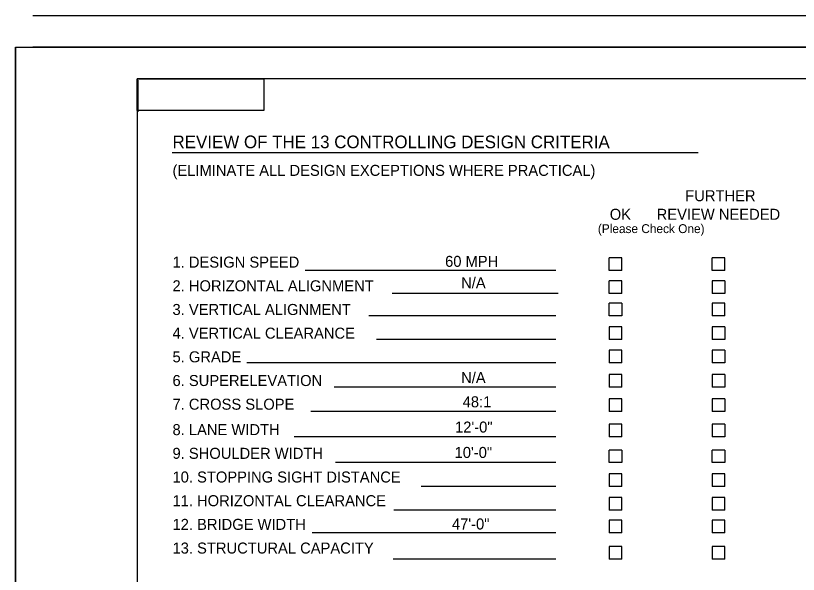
# Model space of a CAD drawing. Extents: x -12279 to -10482, y 3228 to 4378.
# Drawn here: x -12278 to -11660, y 3937 to 4378 of the extents above; entities that cross this region are included whole.
import ezdxf

# ---------------------------------------------------------------- set-up
doc = ezdxf.new("R2010")
doc.units = 0
for name, color, linetype in [('RD_SHT_Bndy', 7, 'Continuous'), ('RD_SHT_IplotShp', 7, 'Continuous'), ('RD_SHT_Snap', 7, 'Continuous'), ('RD_SHT_TX', 7, 'Continuous')]:
    doc.layers.add(name, color=color, linetype=linetype)

msp = doc.modelspace()

# ---------------------------------------------------------------- linework, layer by layer
at = {"layer": 'RD_SHT_Bndy'}
for p, q in [((-10504.69, 4377.98), (-12264.69, 4377.98)), ((-10504.69, 4352.98), (-12264.69, 4352.98)), ((-10507.24, 4327.98), (-12182.24, 4327.98)), ((-12182.24, 4327.98), (-12182.24, 3277.18)), ((-12181.7, 4327.08), (-12181.7, 4302.08)), ((-11738.8, 4269.77), (-12154.49, 4269.77)), ((-11799.22, 4186.64), (-11809.22, 4186.64)), ((-11809.22, 4176.64), (-11809.22, 4186.64)), ((-11799.22, 4176.64), (-11799.22, 4186.64)), ((-11717.68, 4186.64), (-11727.68, 4186.64)), ((-11727.68, 4176.64), (-11727.68, 4186.64)), ((-11717.68, 4176.64), (-11717.68, 4186.64)), ((-11851.36, 4176.64), (-12049.5, 4176.64)), ((-11799.22, 4176.64), (-11809.22, 4176.64)), ((-11717.68, 4176.64), (-11727.68, 4176.64)), ((-11799.22, 4168.7), (-11809.22, 4168.7)), ((-11809.22, 4158.7), (-11809.22, 4168.7)), ((-11799.22, 4158.7), (-11799.22, 4168.7)), ((-11717.68, 4168.7), (-11727.68, 4168.7)), ((-11727.68, 4168.7), (-11727.68, 4158.7)), ((-11717.68, 4168.7), (-11717.68, 4158.7)), ((-11849.4, 4158.7), (-11980.78, 4158.7)), ((-11799.22, 4158.7), (-11809.22, 4158.7)), ((-11717.68, 4158.7), (-11727.68, 4158.7)), ((-11799.22, 4150.89), (-11809.22, 4150.89)), ((-11809.22, 4140.89), (-11809.22, 4150.89)), ((-11799.22, 4150.89), (-11799.22, 4140.89)), ((-11717.68, 4150.89), (-11727.68, 4150.89)), ((-11727.68, 4150.89), (-11727.68, 4140.89)), ((-11717.68, 4140.89), (-11717.68, 4150.89)), ((-11851.36, 4140.89), (-11999.08, 4140.89)), ((-11799.22, 4140.89), (-11809.22, 4140.89)), ((-11717.68, 4140.89), (-11727.68, 4140.89)), ((-11799.22, 4132.2), (-11809.22, 4132.2)), ((-11809.22, 4132.2), (-11809.22, 4122.2)), ((-11799.22, 4122.2), (-11799.22, 4132.2)), ((-11717.68, 4132.2), (-11727.68, 4132.2)), ((-11727.68, 4132.2), (-11727.68, 4122.2)), ((-11717.68, 4132.2), (-11717.68, 4122.2)), ((-11851.36, 4122.2), (-11993.2, 4122.2)), ((-11799.22, 4122.2), (-11809.22, 4122.2)), ((-11717.68, 4122.2), (-11727.68, 4122.2)), ((-11799.22, 4113.86), (-11809.22, 4113.86)), ((-11809.22, 4113.86), (-11809.22, 4103.86)), ((-11799.22, 4103.86), (-11799.22, 4113.86)), ((-11717.68, 4113.86), (-11727.68, 4113.86)), ((-11727.68, 4113.86), (-11727.68, 4103.86)), ((-11717.68, 4113.86), (-11717.68, 4103.86)), ((-11851.36, 4103.86), (-12095.61, 4103.86)), ((-11799.22, 4103.86), (-11809.22, 4103.86)), ((-11717.68, 4103.86), (-11727.68, 4103.86)), ((-11799.22, 4094.62), (-11809.22, 4094.62)), ((-11809.22, 4094.62), (-11809.22, 4084.62)), ((-11799.22, 4084.62), (-11799.22, 4094.62)), ((-11717.68, 4094.62), (-11727.68, 4094.62)), ((-11727.68, 4094.62), (-11727.68, 4084.62)), ((-11717.68, 4094.62), (-11717.68, 4084.62)), ((-11851.36, 4084.62), (-12026.48, 4084.62)), ((-11799.22, 4084.62), (-11809.22, 4084.62)), ((-11717.68, 4084.62), (-11727.68, 4084.62)), ((-11799.22, 4075.28), (-11809.22, 4075.28)), ((-11809.22, 4075.28), (-11809.22, 4065.28)), ((-11799.22, 4065.28), (-11799.22, 4075.28)), ((-11717.68, 4075.28), (-11727.68, 4075.28)), ((-11727.68, 4075.28), (-11727.68, 4065.28)), ((-11717.68, 4075.28), (-11717.68, 4065.28)), ((-11851.36, 4065.28), (-12045.03, 4065.28)), ((-11799.22, 4065.28), (-11809.22, 4065.28)), ((-11717.68, 4065.28), (-11727.68, 4065.28)), ((-11799.22, 4055.4), (-11809.22, 4055.4)), ((-11809.22, 4055.4), (-11809.22, 4045.4)), ((-11799.22, 4045.4), (-11799.22, 4055.4)), ((-11717.68, 4055.4), (-11727.68, 4055.4)), ((-11727.68, 4055.4), (-11727.68, 4045.4)), ((-11717.68, 4055.4), (-11717.68, 4045.4)), ((-11851.36, 4045.4), (-12058.07, 4045.4)), ((-11799.22, 4045.4), (-11809.22, 4045.4)), ((-11717.68, 4045.4), (-11727.68, 4045.4)), ((-11799.22, 4034.99), (-11809.22, 4034.99)), ((-11809.22, 4024.99), (-11809.22, 4034.99)), ((-11799.22, 4034.99), (-11799.22, 4024.99)), ((-11717.68, 4034.99), (-11727.68, 4034.99)), ((-11727.68, 4024.99), (-11727.68, 4034.99)), ((-11717.68, 4034.99), (-11717.68, 4024.99)), ((-11851.36, 4024.99), (-12025.48, 4024.99)), ((-11799.22, 4024.99), (-11809.22, 4024.99)), ((-11717.68, 4024.99), (-11727.68, 4024.99)), ((-11799.22, 4016.19), (-11809.22, 4016.19)), ((-11809.22, 4016.19), (-11809.22, 4006.19)), ((-11799.22, 4006.19), (-11799.22, 4016.19)), ((-11717.68, 4016.19), (-11727.68, 4016.19)), ((-11727.68, 4016.19), (-11727.68, 4006.19)), ((-11717.68, 4006.19), (-11717.68, 4016.19)), ((-11851.36, 4006.19), (-11957.66, 4006.19)), ((-11799.22, 4006.19), (-11809.22, 4006.19)), ((-11717.68, 4006.19), (-11727.68, 4006.19)), ((-11799.22, 3997.39), (-11809.22, 3997.39)), ((-11809.22, 3997.39), (-11809.22, 3987.39)), ((-11799.22, 3987.39), (-11799.22, 3997.39)), ((-11717.68, 3997.39), (-11727.68, 3997.39)), ((-11727.68, 3997.39), (-11727.68, 3987.39)), ((-11717.68, 3987.39), (-11717.68, 3997.39)), ((-11851.36, 3987.39), (-11979.43, 3987.39)), ((-11799.22, 3987.39), (-11809.22, 3987.39)), ((-11717.68, 3987.39), (-11727.68, 3987.39)), ((-11799.22, 3979.66), (-11809.22, 3979.66)), ((-11809.22, 3979.66), (-11809.22, 3969.66)), ((-11799.22, 3969.66), (-11799.22, 3979.66)), ((-11717.68, 3979.66), (-11727.68, 3979.66)), ((-11727.68, 3979.66), (-11727.68, 3969.66)), ((-11717.68, 3969.66), (-11717.68, 3979.66)), ((-11851.36, 3969.66), (-12043.8, 3969.66)), ((-11799.22, 3969.66), (-11809.22, 3969.66)), ((-11717.68, 3969.66), (-11727.68, 3969.66)), ((-11799.22, 3958.71), (-11809.22, 3958.71)), ((-11809.22, 3958.71), (-11809.22, 3948.71)), ((-11799.22, 3948.71), (-11799.22, 3958.71)), ((-11717.68, 3958.71), (-11727.68, 3958.71)), ((-11727.68, 3958.71), (-11727.68, 3948.71)), ((-11717.68, 3948.71), (-11717.68, 3958.71)), ((-11851.36, 3948.71), (-11979.85, 3948.71)), ((-11799.22, 3948.71), (-11809.22, 3948.71)), ((-11717.68, 3948.71), (-11727.68, 3948.71))]:
    msp.add_line(p, q, dxfattribs=at)
msp.add_lwpolyline([(-12182.19, 4302.98), (-12182.19, 4327.98), (-12082.19, 4327.98), (-12082.19, 4302.98)], close=True, dxfattribs=at)
at = {"layer": 'RD_SHT_IplotShp'}
msp.add_lwpolyline([(-12278.24, 4352.98), (-10482.25, 4352.98), (-10482.25, 3252.98), (-12278.24, 3252.98)], close=True, dxfattribs=at)
at = {"layer": 'RD_SHT_Snap'}
msp.add_line((-12278.24, 4352.98), (-12278.24, 3252.98), dxfattribs=at)

# ---------------------------------------------------------------- texts
at = {"layer": 'RD_SHT_TX'}
for s, height, p in [('REVIEW OF THE 13 CONTROLLING DESIGN CRITERIA', 10.001, (-12154.29, 4273.31)), ('(ELIMINATE ALL DESIGN EXCEPTIONS WHERE PRACTICAL)', 8.7001, (-12154.29, 4251.46)), ('FURTHER', 8.7, (-11749.08, 4231.47)), ('OK', 8.7, (-11808.73, 4216.77)), ('REVIEW NEEDED', 8.7001, (-11771.68, 4216.77)), ('(Please Check One)', 7.0001, (-11818.13, 4206.29)), ('1. DESIGN SPEED ', 8.7001, (-12154.29, 4179.01)), ('60 MPH', 8.7, (-11938.87, 4179.6)), ('2. HORIZONTAL ALIGNMENT ', 8.7001, (-12154.29, 4160.31)), ('N/A', 8.7, (-11926.2, 4162.74)), ('3. VERTICAL ALIGNMENT ', 8.7001, (-12154.29, 4141.61)), ('4. VERTICAL CLEARANCE ', 8.7001, (-12154.29, 4122.91)), ('5. GRADE ', 8.7, (-12154.29, 4104.21)), ('N/A', 8.7, (-11926.2, 4087.79)), ('6. SUPERELEVATION ', 8.7001, (-12154.29, 4085.51)), ('48:1', 8.7, (-11924.97, 4068.71)), ('7. CROSS SLOPE ', 8.7001, (-12154.29, 4066.81)), ('8. LANE WIDTH ', 8.7001, (-12154.29, 4046.71)), ('12\'-0"', 8.7, (-11931, 4048.76)), ('9. SHOULDER WIDTH ', 8.7001, (-12154.29, 4028.01)), ('10\'-0"', 8.7, (-11931.34, 4028.71)), ('10. STOPPING SIGHT DISTANCE ', 8.7001, (-12154.29, 4009.31)), ('11. HORIZONTAL CLEARANCE ', 8.7001, (-12154.29, 3990.61)), ('12. BRIDGE WIDTH ', 8.7001, (-12154.29, 3971.91)), ('47\'-0"', 8.7, (-11933.46, 3972.21)), ('13. STRUCTURAL CAPACITY ', 8.7001, (-12154.29, 3953.21))]:
    msp.add_text(s, height=height, dxfattribs=at).set_placement(p)

doc.saveas('drawing.dxf')
